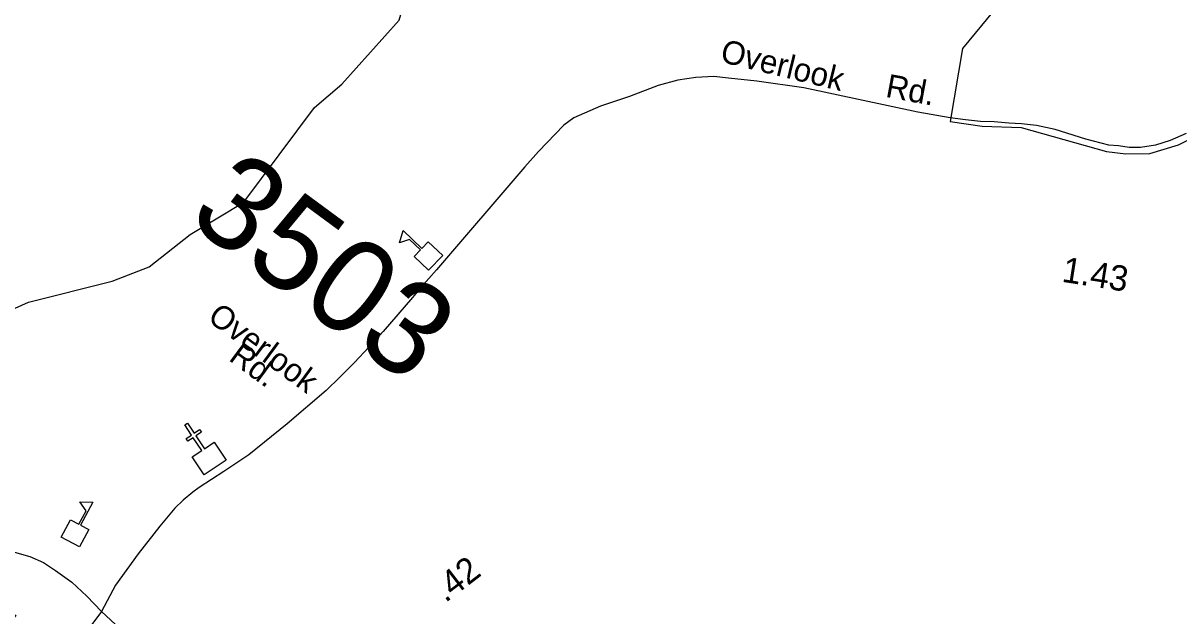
# Model space of a CAD drawing. Extents: x 945666 to 965748, y 644452 to 663300.
# Drawn here: x 953003 to 953745, y 659330 to 659710 of the extents above; entities that cross this region are included whole.
import ezdxf

# ---------------------------------------------------------------- set-up
doc = ezdxf.new("R2010")
doc.units = 0
for name, color, linetype in [('Exist Boundary Political City Limit New', 7, 'Continuous'), ('Exist Cultural Church CELL', 7, 'Continuous'), ('Exist Cultural Educational Facility High CELL', 7, 'Continuous'), ('Exist Hydrographic Creek Single Shore', 7, 'Continuous'), ('Exist Road Primary NC Attributed', 7, 'Continuous'), ('Exist Road Secondary Mileage Tenths English Label', 7, 'Continuous'), ('Exist Road Secondary Type 51 Attributed', 7, 'Continuous'), ('Exist Road Secondary Type 51 Label', 7, 'Continuous'), ('Old_Level_1', 7, 'Continuous')]:
    doc.layers.add(name, color=color, linetype=linetype)

msp = doc.modelspace()

# ---------------------------------------------------------------- linework, layer by layer
at = {"layer": 'Exist Boundary Political City Limit New'}
msp.add_lwpolyline([(953680.14, 659783.92), (953606.21, 659694.05), (953598.2, 659647.27), (953618.74, 659644.08), (953643.7, 659643.27), (953698.5, 659628.02), (953710.82, 659626.37), (953726.36, 659626.53), (953744.79, 659632.28), (953770.6, 659644.99)], dxfattribs=at)
at = {"layer": 'Exist Cultural Church CELL'}
msp.add_lwpolyline([(953111.88, 659431.78), (953118.02, 659435.9), (953112.51, 659444.12), (953109.06, 659441.81), (953107.9, 659443.53), (953111.36, 659445.85), (953107.01, 659452.34), (953108.74, 659453.5), (953113.09, 659447.01), (953116.54, 659449.32), (953117.7, 659447.59), (953114.24, 659445.28), (953119.75, 659437.06), (953125.98, 659441.22), (953133.67, 659429.73), (953119.57, 659420.29)], close=True, dxfattribs=at)
at = {"layer": 'Exist Cultural Educational Facility High CELL'}
for points in [[(953263.48, 659551.64), (953254.25, 659560.4), (953258.37, 659564.74), (953251.3, 659571.46), (953244.81, 659569.19), (953247.13, 659577.14), (953259.23, 659565.64), (953263.35, 659569.98), (953272.57, 659561.22)], [(953027.83, 659380.24), (953033.83, 659391.45), (953039.1, 659388.63), (953043.7, 659397.23), (953039.8, 659402.89), (953048.08, 659402.76), (953040.2, 659388.04), (953045.47, 659385.22), (953039.47, 659374.01)]]:
    msp.add_lwpolyline(points, close=True, dxfattribs=at)
at = {"layer": 'Exist Hydrographic Creek Single Shore'}
msp.add_lwpolyline([(952629.19, 659724.17), (952628.18, 659714.21), (952641.36, 659645.46), (952651.15, 659621.27), (952667.04, 659597.76), (952705.6, 659569.73), (952737.66, 659559.6), (952816.43, 659570), (952829.45, 659563.76), (952898.11, 659510.96), (952923.36, 659504.44), (952953.25, 659507.27), (953006.8, 659531.15), (953060.45, 659544.74), (953084.27, 659553.85), (953110.43, 659574.59), (953144.91, 659595.4), (953190.39, 659656.13), (953207.89, 659671.17), (953244.67, 659712.24), (953264.09, 659778.49), (953259.29, 659854.23)], dxfattribs=at)
at = {"layer": 'Exist Road Primary NC Attributed'}
for points in [[(952802.93, 659360.2), (952816.47, 659355.26), (952827.14, 659352.27), (952837.67, 659350.02), (952851.31, 659348.9), (952861.18, 659349.38), (952871.22, 659350.53), (952911.94, 659358.87), (952929.5, 659362.86), (952967.44, 659371.32), (952976.92, 659372.41), (952990.08, 659371.89), (952997.72, 659370.65), (953007.62, 659367.76), (953016.38, 659363.93), (953024.18, 659358.9), (953034.59, 659351.38), (953044.23, 659342.35), (953053.63, 659332.58)], [(953053.63, 659332.58), (953071.49, 659316.01), (953083.1, 659305.53), (953101.11, 659290.38), (953111.77, 659282.31), (953135.33, 659266.77), (953155.37, 659255.42), (953202.07, 659232.09), (953236.02, 659215.21), (953253.2, 659206.53), (953269.3, 659198.82), (953308.95, 659179.81), (953356.31, 659156.07), (953407.63, 659128.93), (953446.02, 659108.53), (953464.07, 659099.3), (953475.58, 659093.45), (953481.88, 659090.88), (953498.47, 659085.2)]]:
    msp.add_lwpolyline(points, dxfattribs=at)
at = {"layer": 'Exist Road Secondary Type 51 Attributed'}
for points in [[(953749.71, 659639.48), (953739.41, 659634.94), (953729.9, 659631.97), (953720.37, 659630.39), (953712.98, 659630.54), (953706.14, 659631.66), (953699.94, 659631.96), (953685.18, 659635.89), (953665.64, 659642.15), (953653.68, 659644.57), (953643.88, 659645.66), (953635.9, 659646.2), (953626.45, 659646.92), (953617.69, 659647.14), (953608.09, 659648.16), (953598.24, 659649.54), (953577.45, 659653.28), (953504.3, 659668.71), (953474.09, 659673.16), (953456.03, 659675.06), (953446.63, 659676.11), (953435.04, 659675.38), (953423.37, 659673.66), (953410.85, 659670.39), (953392.43, 659663.3), (953373.76, 659657.09), (953356.74, 659649.49), (953350.38, 659644.73), (953334.04, 659627.9), (953325.25, 659618.15), (953268.53, 659551.87), (953263.69, 659546.32), (953258.51, 659540.48), (953253.11, 659534.13), (953234.46, 659512.22), (953225.19, 659502.2), (953215.9, 659492.38), (953206.56, 659483.07), (953197.82, 659474.52), (953172.84, 659452.94), (953148.27, 659433.2), (953132.22, 659422.31), (953116.31, 659412.11), (953112.14, 659409.12), (953105.98, 659404.03), (953100.76, 659398.88), (953091.1, 659387.36), (953077.23, 659369.51), (953062.6, 659349.35), (953053.63, 659332.58)], [(953053.63, 659332.58), (953033.9, 659306.14), (953029.53, 659300.72), (953026.83, 659298.16), (953025.18, 659295.19), (953025.8, 659292.41), (953028.04, 659287.1), (953028.27, 659283.91), (953028.09, 659277.98), (953026.04, 659273.87), (953021.44, 659268.97), (953016.06, 659264.82)]]:
    msp.add_lwpolyline(points, dxfattribs=at)

# ---------------------------------------------------------------- texts
at = {"layer": 'Exist Road Secondary Mileage Tenths English Label'}
for s, rotation, p in [('1.43', 351.07954, (953669.33, 659544.34)), ('.42', 37.54851, (953274.34, 659337.81))]:
    msp.add_text(s, height=16.238, rotation=rotation, dxfattribs=at).set_placement(p)
at = {"layer": 'Exist Road Secondary Type 51 Label'}
for s, rotation, p in [('Overlook', 346.28242, (953450, 659685.68)), ('Rd.', 349.45166, (953556.17, 659663.07)), ('Overlook', 323.59084, (953120.9, 659519.69)), ('Rd.', 323.59084, (953134.61, 659494.22)), ('Overlook', 323.59084, (952952.35, 659344.86))]:
    msp.add_text(s, height=15, rotation=rotation, dxfattribs=at).set_placement(p)
at = {"layer": 'Old_Level_1'}
msp.add_text('3503', height=60, rotation=323.59084, dxfattribs=at).set_placement((953107.37, 659583.45))

doc.saveas('drawing.dxf')
